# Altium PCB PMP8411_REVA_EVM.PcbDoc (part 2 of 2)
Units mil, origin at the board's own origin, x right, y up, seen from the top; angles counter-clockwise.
Board outline 4000 x 4000 mil, 6 copper layers (Top Layer, Mid-Layer 1, Mid-Layer 2, Mid-Layer 3, Mid-Layer 4, Bottom Layer), stack 118 mil thick; 118 components, 65 nets, 370 pads, 398 vias.
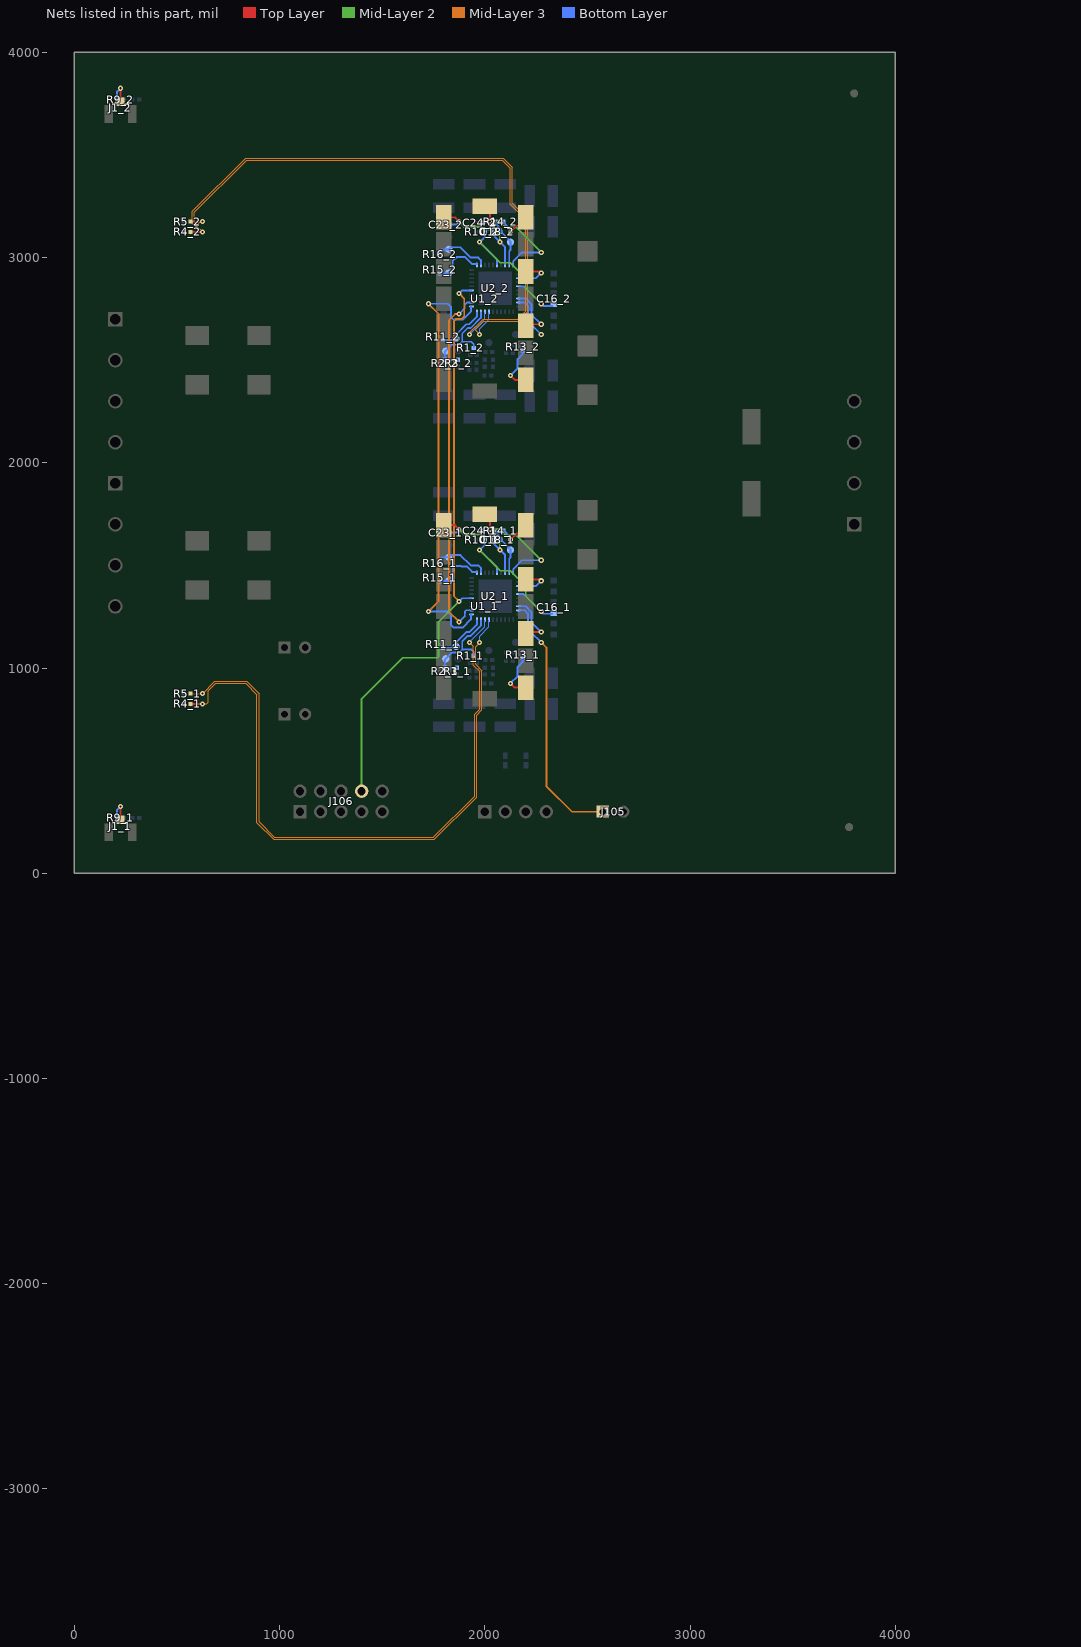
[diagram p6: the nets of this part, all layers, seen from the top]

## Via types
v1: diameter 25, hole 10, Top Layer to Bottom Layer, 378 vias
v2: diameter 19.68, hole 7.87, Top Layer to Bottom Layer, 16 vias
v3: diameter 23, hole 10, Top Layer to Bottom Layer, 4 vias

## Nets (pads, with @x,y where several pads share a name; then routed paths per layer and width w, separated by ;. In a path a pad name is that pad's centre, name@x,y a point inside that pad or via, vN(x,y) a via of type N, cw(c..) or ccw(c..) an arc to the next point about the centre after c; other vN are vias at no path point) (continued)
NetC16_1_1: C16_1.1 R10_1.2 U2_1.16 U2_1.25 | length 859.3
  Mid-Layer 2 w7: v1(1975,1575) 2074.99,1475.01 2124.99,1475.01 2200,1400 2200,1350 v1(2275,1275)
  Bottom Layer w7: v1(2275,1275) 2285.25,1264.75 C16_1.1@2331.25,1264.75
  Bottom Layer w9: R10_1.2@2001.5,1625 2001.5,1601.5 v1(1975,1575) 2059.84,1490.16 U2_1.16@2059.84,1468 ; U2_1.25@2168,1359.84 2190.16,1359.84 v1(2275,1275)
NetC16_2_1: C16_2.1 R10_2.2 U2_2.16 U2_2.25 | length 859.3
  Mid-Layer 2 w7: v1(1975,3075) 2074.99,2975.01 2124.99,2975.01 2200,2900 2200,2850 v1(2275,2775)
  Bottom Layer w9: R10_2.2@2001.5,3125 2001.5,3101.5 v1(1975,3075) 2059.84,2990.16 U2_2.16@2059.84,2968 ; U2_2.25@2168,2859.84 2190.16,2859.84 v1(2275,2775) 2285.25,2764.75 C16_2.1@2331.25,2764.75
NetC18_1_1: C18_1.1 pad.0@2125,1575 R14_1.1 U2_1.19 | length 232.1
  Bottom Layer w9: R14_1.1@2058.5,1670 2058.5,1656.5 2079,1636 2079,1625 2125,1579 pad.0@2125,1575 2125,1537.5 2118.88,1531.38 U2_1.19@2118.88,1468
NetC18_1_2: C18_1.2 C23_1.1 U1_1.7 U2_1.18 | length 578.2
  Top Layer w10: U1_1.7@1799,1696 1854,1696 v1(1875,1675)
  Mid-Layer 2 w10: v1(1875,1675) 1900,1650 1975,1650 1987.5,1637.5 2043.75,1637.5 2075,1606.25 v1(2075,1575)
  Bottom Layer w10: C23_1.1@1826.5,1660 1860,1660 v1(1875,1675) ; C18_1.2@2046,1625 2046,1604 v1(2075,1575) 2099.2,1550.8 U2_1.18@2099.2,1468
NetC18_2_1: C18_2.1 pad.0@2125,3075 R14_2.1 U2_2.19 | length 232.1
  Bottom Layer w9: R14_2.1@2058.5,3170 2058.5,3159 2079,3138.5 2079,3125 2125,3079 pad.0@2125,3075 2125,3037.5 2118.88,3031.38 U2_2.19@2118.88,2968
NetC18_2_2: C18_2.2 C23_2.1 U1_2.7 U2_2.18 | length 578.2
  Top Layer w9: U1_2.7@1799,3196 1854,3196 v1(1875,3175)
  Mid-Layer 2 w10: v1(1875,3175) 1900,3150 1975,3150 1987.5,3137.5 2043.75,3137.5 2075,3106.25 v1(2075,3075)
  Bottom Layer w9: C18_2.2@2046,3125 2046,3104 v1(2075,3075) 2099.2,3050.8 U2_2.18@2099.2,2968
  Bottom Layer w10: C23_2.1@1826.5,3160 1860,3160 v1(1875,3175)
NetC24_1_1: C24_1.1 U1_1.16 U2_1.20 | length 602.5
  Top Layer w9: U1_1.16@2000,1751 2025,1726 v1(2025,1675)
  Mid-Layer 2 w7: v1(2025,1675) 2075,1675 2100,1650 2150,1650 v1(2275,1525)
  Bottom Layer w9: C24_1.1@1991.5,1670 2020,1670 v1(2025,1675) ; U2_1.20@2138.56,1468 2138.56,1482.31 2181.25,1525 v1(2275,1525)
NetC24_2_1: C24_2.1 U1_2.16 U2_2.20 | length 602.5
  Top Layer w9: U1_2.16@2000,3251 2025,3226 v1(2025,3175)
  Mid-Layer 2 w7: v1(2025,3175) 2075,3175 2100,3150 2150,3150 v1(2275,3025)
  Bottom Layer w9: C24_2.1@1991.5,3170 2020,3170 v1(2025,3175) ; U2_2.20@2138.56,2968 2138.56,2982.31 2181.25,3025 v1(2275,3025)
NetJ1_1_1: J1_1.1 R9_1.1 | length 122.3
  Top Layer w9: J1_1.1@225,259.5 v1(225,325)
  Bottom Layer w9: R9_1.1@208.5,275 208.5,308.5 v1(225,325)
NetJ1_2_1: J1_2.1 R9_2.1 | length 122.3
  Top Layer w9: J1_2.1@225,3759.5 v1(225,3825)
  Bottom Layer w9: R9_2.1@208.5,3775 208.5,3808.5 v1(225,3825)
NetR1_1_1: pad.0@1810,1045 R1_1.1 R2_1.2 R3_1.2 U2_1.39 | length 472.5
  Bottom Layer w9: R3_1.2@1865,1001.5 R2_1.2@1805,1001.5 1805,1040 pad.0@1810,1045 1840,1075 1875,1075 1890,1090 ; R1_1.1@1946.5,1060 1946.5,1078.5 1935,1090 1890,1090 ; U2_1.39@1981.12,1232 1981.12,1206.12 1931.73,1156.73 1916.73,1156.73 1890,1130 1890,1090
NetR1_2_1: pad.0@1810,2545 R1_2.1 R2_2.2 R3_2.2 U2_2.39 | length 472.5
  Bottom Layer w9: R3_2.2@1865,2501.5 R2_2.2@1805,2501.5 1805,2540 pad.0@1810,2545 1840,2575 1875,2575 1890,2590 ; R1_2.1@1946.5,2560 1946.5,2578.5 1935,2590 1890,2590 ; U2_2.39@1981.12,2732 1981.12,2706.12 1931.73,2656.73 1916.73,2656.73 1890,2630 1890,2590
NetR4_1_2: R4_1.2 U2_1.37 | length 3144.6
  Top Layer w9: R4_1.2@566.5,825 v1(625,825)
  Mid-Layer 3 w4.49: v1(625,825) 644.49,825 652.67,833.18 652.67,888.53 689.14,925 835.86,925 890,870.86 890,245.86 970.86,165 1754.14,165 1960,370.86 1960,770.86 1985,795.86 1985,987.43 1955,1017.43 1955,1104.14 1975,1124.14 v1(1975,1125)
  Bottom Layer w5: v1(1975,1125) 1975,1155 2020.48,1200.48 U2_1.37@2020.48,1232
NetR4_2_2: R4_2.2 U2_2.37 | length 3056.4
  Top Layer w9: R4_2.2@566.5,3125 v1(625,3125)
  Mid-Layer 3 w4.49: v1(625,3125) 597.68,3152.32 590.86,3152.32 575,3168.18 575,3225 835,3485 2090,3485 2135,3440 2135,3265 2210,3190 2210,2735 2165,2690 1995.5,2690 1952.93,2647.43 1952.93,2647.07 v1(1975,2625)
  Bottom Layer w5: v1(1975,2625) 1975,2653.79 2015.8,2694.59 2015.8,2695.8 2020.48,2700.48 U2_2.37@2020.48,2732
NetR5_1_2: R5_1.2 U2_1.38 | length 3091.6
  Top Layer w5: R5_1.2@566.5,875 v1(625,875)
  Mid-Layer 3 w4.49: v1(625,875) 685,935 840,935 900,875 900,250 975,175 1750,175 1950,375 1950,775 1975,800 1975,983.29 1945,1013.29 1945,1105 v1(1925,1125)
  Bottom Layer w5: v1(1925,1125) 2000.8,1200.8 U2_1.38@2000.8,1232
NetR5_2_2: R5_2.2 U2_2.38 | length 3021.9
  Top Layer w5: R5_2.2@565,3175 R5_2.2@566.5,3175 v1@623.5,3175
  Mid-Layer 3 w4.49: 601.82,3162.32 595,3162.32 585,3172.32 585,3220.86 839.14,3475 2085.86,3475 2125,3435.86 2125,3260.86 2200,3185.86 2200,2739.14 2160.86,2700 1991.36,2700 1925,2633.64 v1(1925,2625) ; v1@614.5,3175 v1(625,3175)
  Mid-Layer 3 w5: 601.82,3162.32 614.5,3175 v1(625,3175)
  Bottom Layer w5: v1(1925,2625) 2000.8,2700.8 U2_2.38@2000.8,2732
NetR11_1_2: pad.0@1860,1105 R11_1.2 U2_1.40 | length 245.5
  Bottom Layer w9: R11_1.2@1795,1098.5 1853.5,1098.5 pad.0@1860,1105 1860,1125 1910,1175 1925,1175 1961.44,1211.44 U2_1.40@1961.44,1232
NetR11_2_2: pad.0@1860,2605 R11_2.2 U2_2.40 | length 245.5
  Bottom Layer w9: R11_2.2@1795,2598.5 1853.5,2598.5 pad.0@1860,2605 1860,2625 1910,2675 1925,2675 1961.44,2711.44 U2_2.40@1961.44,2732
NetR13_1_2: R13_1.2 U1_1.14 | length 233.1
  Top Layer w10: v1(2125,925) 2146,904 U1_1.14@2201,904
  Bottom Layer w10: v1(2125,925) 2160,960 2160,1005 2185,1030 R13_1.2@2185,1048.5
NetR13_2_2: R13_2.2 U1_2.14 | length 233.1
  Top Layer w9: v1(2125,2425) 2146,2404 U1_2.14@2201,2404
  Bottom Layer w9: v1(2125,2425) 2160,2460 2160,2505 2185,2530 R13_2.2@2185,2548.5
NetR14_1_2: R14_1.2 U1_1.8 | length 176
  Top Layer w10: v1(2125,1625) 2155,1655 2180,1655 2201,1676 U1_1.8@2201,1696
  Bottom Layer w10: R14_1.2@2091.5,1670 2125,1636.5 v1(2125,1625)
NetR14_2_2: R14_2.2 U1_2.8 | length 176
  Top Layer w9: v1(2125,3125) 2155,3155 2180,3155 2201,3176 U1_2.8@2201,3196
  Bottom Layer w9: R14_2.2@2091.5,3170 2125,3136.5 v1(2125,3125)
NetR15_1_2: pad.0@1825,1425 R15_1.2 U2_1.11 | length 247.1
  Bottom Layer w9: R15_1.2@1780,1423.5 1823.5,1423.5 pad.0@1825,1425 1843.75,1443.75 1843.75,1483.35 1857.4,1497 1884.11,1497 1886.11,1495 1911.25,1495 1938.25,1468 U2_1.11@1961.44,1468
NetR15_2_2: pad.0@1825,2925 R15_2.2 U2_2.11 | length 251.2
  Bottom Layer w9: R15_2.2@1781.25,2922.25 1822.25,2922.25 pad.0@1825,2925 1843.75,2943.75 1843.75,2983.75 1862.5,3002.5 1903.75,3002.5 1938.25,2968 U2_2.11@1961.44,2968
NetR16_1_2: pad.0@1825,1540 R16_1.2 U2_1.12 | length 254
  Bottom Layer w9: R16_1.2@1781.25,1529 1792.25,1540 pad.0@1825,1540 1835,1550 1881.25,1550 1931.25,1500 1968.75,1500 1981.12,1487.63 U2_1.12@1981.12,1468
NetR16_2_2: pad.0@1825,3040 R16_2.2 U2_2.12 | length 254
  Bottom Layer w9: R16_2.2@1781.25,3029 1792.25,3040 pad.0@1825,3040 1835,3050 1881.25,3050 1931.25,3000 1968.75,3000 1981.12,2987.63 U2_2.12@1981.12,2968
NetU1_1_10: U1_1.10 U2_1.23 | length 194.6
  Top Layer w9: U1_1.10@2201,1432 2268,1432 v1(2275,1425)
  Bottom Layer w9: U2_1.23@2168,1399.2 2249.2,1399.2 v1(2275,1425)
NetU1_1_12: U1_1.12 U2_1.28 | length 265.3
  Top Layer w9: U1_1.12@2201,1168 2208,1175 v1(2275,1175)
  Bottom Layer w9: U2_1.28@2168,1300.8 2199.2,1300.8 2227.5,1272.5 2227.5,1222.5 v1(2275,1175)
NetU1_2_10: U1_2.10 U2_2.23 | length 194.6
  Top Layer w9: U1_2.10@2201,2932 2268,2932 v1(2275,2925)
  Bottom Layer w9: U2_2.23@2168,2899.2 2249.2,2899.2 v1(2275,2925)
NetU1_2_12: U1_2.12 U2_2.28 | length 265.3
  Top Layer w9: U1_2.12@2200,2668 U1_2.12@2207,2675 ; U1_2.12@2208,2675 v1(2275,2675)
  Bottom Layer w9: U2_2.28@2168,2800.8 2199.2,2800.8 2227.5,2772.5 2227.5,2722.5 v1(2275,2675)
PG1: J105.1 U2_1.29 | length 1252.7
  Mid-Layer 3 w9: v1(2275,1125) 2300,1100 2300,425 2425,300 J105.1@2575,300
  Bottom Layer w9: U2_1.29@2168,1281.12 2193.88,1281.12 2210,1265 2210,1210 2225,1195 2225,1175 v1(2275,1125)
PG1_NC: U2_2.29 | length 215.6
  Bottom Layer w9: U2_2.29@2168,2781.12 2193.88,2781.12 2210,2765 2210,2710 2225,2695 2225,2675 v1(2275,2625)
PHSET: U2_1.2 U2_2.2 | length 1737.5
  Mid-Layer 3 w9: v1(1875,1225) 1825,1275 1825,2695 1855,2725 v1(1875,2725)
  Bottom Layer w9: v1(1875,1225) 1903,1253 1903,1254.52 1902.5,1255.02 1902.5,1267.86 1903,1268.36 1903,1275.5 1908.62,1281.12 U2_1.2@1932,1281.12 ; v1(1875,2725) 1902.5,2752.5 1902.5,2770 1913.62,2781.12 U2_2.2@1932,2781.12
SMBAL: J106.8 U2_1.5 U2_2.5 | length 2904.8
  Mid-Layer 2 w9: J106.8@1400,400 1400,850 1600,1050 1770.5,1050 1775,1054.5 1775,1225 v1(1875,1325)
  Mid-Layer 3 w9: v1(1875,1325) 1850,1350 1850,2690 1860,2700 1886,2700 1900,2714 1900,2800 v1(1875,2825)
  Bottom Layer w9: v1(1875,1325) 1890.16,1340.16 U2_1.5@1932,1340.16 ; v1(1875,2825) 1890.16,2840.16 U2_2.5@1932,2840.16
SYNC: U2_1.1 U2_2.1 | length 2160.2
  Mid-Layer 3 w9: v1(1725,1275) 1775,1325 1775,2725 v1(1725,2775)
  Bottom Layer w9: v1(1725,1275) 1820,1275 1835,1260 1835,1210 1848,1197 1892,1197 1932,1237 U2_1.1@1932,1261.44 ; v1(1725,2775) 1820,2775 1835,2760 1835,2710 1847.5,2697.5 1892.5,2697.5 1932,2737 U2_2.1@1932,2761.44
pads on no net: FID100.1 FID101.1 J106.1 J106.2 J106.3 J106.4 U2_1.4 U2_1.22 U2_2.4 U2_2.22

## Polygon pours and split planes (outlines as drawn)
+1.0V on Bottom Layer "BOTTOM-P0_9V_SM0_VDD" (solid, pour order 2): 1675,675 1675,1900 2155,1900 2155,1805 1740,1805 1740,1560 1740,1555 1740,1415 1730,1405 1710,1405 1700,1395 1700,1380.04 1699.96,1379.85 1699.64,1377.65 1699.5,1375.43 1699.56,1373.2 1699.81,1370.99 1699.96,1370.15 1700,1369.96 1700,1330.04 1699.96,1329.85 1699.64,1327.65 1699.5,1325.43 1699.56,1323.2 1699.81,1320.99 1699.96,1320.15 1700,1319.96 1700,1280.04 1699.96,1279.85 1699.64,1277.65 1699.5,1275.43 1699.56,1273.2 1699.81,1270.99 1699.96,1270.15 1700,1269.96 1700,1210 1710,1200 1770,1200 1770,995 1740,965 1740,790 2155,790 2155,675 1675,675
+1.0V on Bottom Layer "BOTTOM-P0_9V_SM0_VDD 1" (solid, pour order 8): 1675,2175 1675,3400 2155,3400 2155,3305 1740,3305 1740,3060 1740,3055 1740,2915 1730,2905 1710,2905 1700,2895 1700,2880.04 1699.96,2879.85 1699.64,2877.65 1699.5,2875.43 1699.56,2873.2 1699.81,2870.99 1699.96,2870.15 1700,2869.96 1700,2830.04 1699.96,2829.85 1699.64,2827.65 1699.5,2825.43 1699.56,2823.2 1699.81,2820.99 1699.96,2820.15 1700,2819.96 1700,2780.04 1699.96,2779.85 1699.64,2777.65 1699.5,2775.43 1699.56,2773.2 1699.81,2770.99 1699.96,2770.15 1700,2769.96 1700,2710 1710,2700 1770,2700 1770,2495 1740,2465 1740,2290 2155,2290 2155,2175 1675,2175
+1.0V on Bottom Layer "BOTTOM-P0_9V_SM0_VDD 2" (solid, pour order 12): 1700,2869.96 1700,2830.04 1699.96,2829.85 1699.64,2827.65 1699.5,2825.43 1699.56,2823.2 1699.81,2820.99 1699.96,2820.15 1700,2819.96 1700,2780.04 1699.96,2779.85 1699.64,2777.65 1699.5,2775.43 1699.56,2773.2 1699.81,2770.99 1699.96,2770.15 1700,2769.96 1700,2200 2075,2200 2075,1875 1700,1875 1700,1380.04 1699.96,1379.85 1699.64,1377.65 1699.5,1375.43 1699.56,1373.2 1699.81,1370.99 1699.96,1370.15 1700,1369.96 1700,1330.04 1699.96,1329.85 1699.64,1327.65 1699.5,1325.43 1699.56,1323.2 1699.81,1320.99 1699.96,1320.15 1700,1319.96 1700,1280.04 1699.96,1279.85 1699.64,1277.65 1699.5,1275.43 1699.56,1273.2 1699.81,1270.99 1699.96,1270.15 1700,1269.96 1700,675 1494.59,675 1494.42,676.81 1494.19,678.5 1493.81,680.16 1493.29,681.78 1492.63,683.35 1491.83,684.85 1490.91,686.28 1489.87,687.62 1488.71,688.87 1487.45,690.01 1486.09,691.04 1484.65,691.95 1483.14,692.72 1481.56,693.36 1479.94,693.87 1478.27,694.23 1476.59,694.44 1474.89,694.5 1473.19,694.42 1471.5,694.19 1469.84,693.81 1468.22,693.29 1466.65,692.63 1465.15,691.83 1463.72,690.91 1462.38,689.87 1461.13,688.71 1459.99,687.45 1458.96,686.09 1458.05,684.65 1457.28,683.14 1456.64,681.56 1456.13,679.94 1455.77,678.27 1455.58,676.81 1455.41,675 1300,675 1300,1600 100,1600 100,2400 1300,2400 1300,3400 1700,3400 1700,2880.04 1699.96,2879.85 1699.64,2877.65 1699.5,2875.43 1699.56,2873.2 1699.81,2870.99 1699.96,2870.15 1700,2869.96
IBV on Bottom Layer "BOTTOM-IBV" (solid, pour order 20): 2350,675 2350,1000 2410,1000 2410,875 2590,875 2590,1000 2700,1000 2700,1600 2590,1600 2590,1725 2410,1725 2410,1600 2350,1600 2350,2500 2410,2500 2410,2375 2590,2375 2590,2500 2700,2500 2700,3100 2590,3100 2590,3225 2410,3225 2410,3100 2350,3100 2350,3400 3000,3400 3000,2500 3900,2500 3900,2000 3000,2000 3000,675 2350,675
IBV on Bottom Layer "BOTTOM-IBV 1" (solid, pour order 24): 2260,3050 2260,3065 2260,3400 2375,3400 2375,3050 2280.04,3050 2279.85,3050.04 2277.65,3050.36 2275.43,3050.5 2273.2,3050.44 2270.99,3050.19 2270.15,3050.04 2269.96,3050 2260,3050
IBV on Bottom Layer "BOTTOM-IBV 2" (solid, pour order 26): 2260,2175 2260,2510 2260,2540 2307.68,2540 2375,2540 2375,2175 2260,2175
IBV on Bottom Layer "BOTTOM-IBV 3" (solid, pour order 32): 2260,675 2260,1040 2307.68,1040 2375,1040 2375,675 2260,675
IBV on Bottom Layer "BOTTOM-IBV 4" (solid, pour order 34): 2260,1550 2260,1900 2375,1900 2375,1550 2280.04,1550 2279.85,1550.04 2277.65,1550.36 2275.43,1550.5 2273.2,1550.44 2270.99,1550.19 2270.15,1550.04 2269.96,1550 2260,1550
GND on Bottom Layer "BOTTOM-GND" (solid, pour order 48): 2175,625 2175,700 2250,700 2250,665 2250,625 2175,625
GND on Bottom Layer "BOTTOM-GND 1" (solid, pour order 50): 2175,3375 2175,3450 2250,3450 2250,3410 2250,3375 2175,3375
GND on Bottom Layer "BOTTOM-GND 2" (solid, pour order 52): 2175,1875 2175,1950 2250,1950 2250,1910 2250,1875 2175,1875
GND on Bottom Layer "BOTTOM-GND 3" (solid, pour order 54): 2175,2125 2175,2200 2250,2200 2250,2165 2250,2125 2175,2125
GND on Bottom Layer "BOTTOM-GND 4" (solid, pour order 56): 2325,2150 2325,1925 2100,1925 2100,2150 2325,2150
GND on Bottom Layer "BOTTOM-GND 5" (solid, pour order 58): 2400,2525 2400,3075 2410,3075 2590,3075 2675,3075 2675,2525 2590,2525 2410,2525 2400,2525
GND on Bottom Layer "BOTTOM-GND 6" (solid, pour order 60): 2400,1025 2400,1575 2410,1575 2590,1575 2675,1575 2675,1025 2590,1025 2410,1025 2400,1025
GND on Bottom Layer "BOTTOM-GND 7" (solid, pour order 64): 2155,1575 2155,1630 2146.85,1638.15 2145.62,1640 2144.23,1641.74 2142.7,1643.36 2141.03,1644.83 2139.25,1646.15 2138.35,1646.73 2138.15,1646.85 2115,1670 2115,1690 2105,1700 1850,1700 1835,1685 1750,1685 1750,1795 2165,1795 2165,1900 2250,1900 2250,1575 2155,1575
GND on Bottom Layer "BOTTOM-GND 8" (solid, pour order 66): 2165,675 2165,800 1750,800 1750,890 2155,890 2185,920 2185,1000 2250,1000 2250,675 2165,675
GND on Bottom Layer "BOTTOM-GND 9" (solid, pour order 76): 100,100 100,1575 510,1575 510,1425 690,1425 690,1575 810,1575 810,1425 990,1425 990,1575 1275,1575 1275,650 3025,650 3025,1975 3900,1975 3900,100 100,100
GND on Bottom Layer "BOTTOM-GND 10" (solid, pour order 78): 100,2425 100,3900 3900,3900 3900,2525 3025,2525 3025,3425 1275,3425 1275,2425 990,2425 990,2575 810,2575 810,2425 690,2425 690,2575 510,2575 510,2425 100,2425
GND on Bottom Layer "BOTTOM-GND 11" (solid, pour order 80): 2165,2175 2165,2300 1750,2300 1750,2390 2155,2390 2185,2420 2185,2500 2250,2500 2250,2175 2165,2175
GND on Bottom Layer "BOTTOM-GND 12" (solid, pour order 82): 2155,3075 2155,3130 2146.85,3138.15 2146.73,3138.35 2145.48,3140.19 2144.08,3141.92 2142.54,3143.52 2140.85,3144.97 2139.05,3146.28 2138.35,3146.73 2138.15,3146.85 2115,3170 2115,3190 2105,3200 1850,3200 1835,3185 1750,3185 1750,3295 2165,3295 2165,3400 2250,3400 2250,3075 2155,3075
+1.0V on Top Layer "TOP-P0_9V_SM0_VDD" (solid, pour order 4): 1675,675 1675,1900 2075,1900 2075,1800 1850,1800 1850,1755 1755,1755 1755,1753.5 1754,1753.5 1754,1638.5 1755,1638.5 1755,1495 1850,1495 1850,1360 1755,1360 1755,1400 1700,1400 1700,1360 1700,1300 1700,1250 1700,1200 1755,1200 1755,1225 1770,1240 1850,1240 1850,1105 1755,1105 1755,961.5 1754,961.5 1754,846.5 1755,846.5 1755,840 1850,840 1850,800 2075,800 2075,675 1675,675
+1.0V on Top Layer "TOP-P0_9V_SM0_VDD 1" (solid, pour order 6): 1675,2175 1675,3400 2075,3400 2075,3300 1850,3300 1850,3255 1755,3255 1755,3253.5 1754,3253.5 1754,3138.5 1755,3138.5 1755,2995 1850,2995 1850,2860 1755,2860 1755,2900 1700,2900 1700,2860 1700,2800 1700,2750 1700,2700 1755,2700 1755,2725 1770,2740 1850,2740 1850,2605 1755,2605 1755,2461.5 1754,2461.5 1754,2346.5 1755,2346.5 1755,2340 1850,2340 1850,2300 2075,2300 2075,2175 1675,2175
+1.0V on Top Layer "TOP-P0_9V_SM0_VDD 2" (solid, pour order 14): 1455.41,675 1300,675 1300,1600 100,1600 100,2400 1300,2400 1300,3400 1700,3400 1700,2200 2075,2200 2075,2165 2075,1910 2075,1875 1700,1875 1700,675 1494.59,675 1494.42,676.81 1494.19,678.5 1493.81,680.16 1493.29,681.78 1492.63,683.35 1491.83,684.85 1490.91,686.28 1489.87,687.62 1488.71,688.87 1487.45,690.01 1486.09,691.04 1484.65,691.95 1483.14,692.72 1481.56,693.36 1479.94,693.87 1478.27,694.23 1476.59,694.44 1474.89,694.5 1473.19,694.42 1471.5,694.19 1469.84,693.81 1468.22,693.29 1466.65,692.63 1465.15,691.83 1463.72,690.91 1462.38,689.87 1461.13,688.71 1459.99,687.45 1458.96,686.09 1458.05,684.65 1457.28,683.14 1456.64,681.56 1456.13,679.94 1455.77,678.27 1455.58,676.81 1455.41,675
IBV on Top Layer "TOP-IBV" (solid, pour order 28): 2250,2175 2250,2355 2250,2465 2150,2465 2150,2600 2375,2600 2375,2175 2250,2175
IBV on Top Layer "TOP-IBV 1" (solid, pour order 30): 2250,1900 2375,1900 2375,1550 2265,1550 2250,1535 2250,1495 2155,1495 2155,1635 2250,1635 2250,1900
IBV on Top Layer "TOP-IBV 2" (solid, pour order 36): 2350,675 2350,1000 2410,1000 2410,875 2590,875 2590,1000 2700,1000 2700,1600 2590,1600 2590,1725 2410,1725 2410,1600 2350,1600 2350,2500 2410,2500 2410,2375 2590,2375 2590,2500 2700,2500 2700,3100 2590,3100 2590,3225 2410,3225 2410,3100 2350,3100 2350,3400 3000,3400 3000,2500 3900,2500 3900,2000 3332,2000 3332,2050 3268,2050 3268,2000 3000,2000 3000,675 2350,675
IBV on Top Layer "TOP-IBV 3" (solid, pour order 38): 2150,965 2150,1100 2375,1100 2375,675 2250,675 2250,965 2150,965
IBV on Top Layer "TOP-IBV 4" (solid, pour order 40): 2155,2995 2155,3110 2155,3135 2250,3135 2250,3245 2250,3400 2375,3400 2375,3050 2265.86,3050 2265,3050 2250,3035 2250,3034.15 2250,3034.14 2250,2995 2155,2995
GND on Top Layer "TOP-GND" (solid, pour order 42): 2100,1875 2100,2200 2240,2200 2240,2165 2325,2165 2325,1910 2240,1910 2240,1875 2100,1875
GND on Top Layer "TOP-GND 1" (solid, pour order 44): 2385,1025 2385,1110 2350,1110 2350,1540 2385,1540 2385,1575 2410,1575 2590,1575 2675,1575 2675,1025 2590,1025 2410,1025 2385,1025
GND on Top Layer "TOP-GND 2" (solid, pour order 46): 2385,2525 2385,2610 2350,2610 2350,3040 2385,3040 2385,3075 2410,3075 2590,3075 2675,3075 2675,2525 2590,2525 2410,2525 2385,2525
GND on Top Layer "TOP-GND 3" (solid, pour order 68): 2090,630 2090,700 2240,700 2240,665 2240,630 2090,630
GND on Top Layer "TOP-GND 4" (solid, pour order 70): 2240,3450 2240,3360 2090,3360 2090,3450 2240,3450
GND on Top Layer "TOP-GND 5" (solid, pour order 72): 100,100 100,1575 510,1575 510,1425 690,1425 690,1575 810,1575 810,1425 990,1425 990,1575 1275,1575 1275,650 3025,650 3025,1975 3268,1975 3268,1950 3332,1950 3332,1975 3900,1975 3900,100 100,100
GND on Top Layer "TOP-GND 6" (solid, pour order 74): 100,2425 100,3900 3900,3900 3900,2525 3025,2525 3025,3425 1275,3425 1275,2425 990,2425 990,2575 810,2575 810,2425 690,2425 690,2575 510,2575 510,2425 100,2425
GND on Top Layer "TOP-GND 7" (solid, pour order 84): 964 vertices, not listed, extent 1765,2175 2375,3400
GND on Top Layer "TOP-GND 8" (solid, pour order 86): 963 vertices, not listed, extent 1765,675 2375,1900
+1.0V on Mid-Layer 4 "P05-P0_9V_SM0_VDD" (solid, pour order 10): 2200,100 100,100 100,3900 2200,3900 2200,100
IBV on Mid-Layer 4 "P05-IBV" (solid, pour order 16): 2250,700 2550,700 2550,850 2425,850 2425,1775 2575,1775 2575,1925 2250,1925 2250,700
IBV on Mid-Layer 4 "P05-IBV 1" (solid, pour order 18): 2250,2200 2550,2200 2550,2350 2425,2350 2425,3275 2575,3275 2575,3425 2250,3425 2250,2200
IBV on Mid-Layer 4 "P05-IBV 2" (solid, pour order 22): 2210,338.73 2210,3900 3900,3900 3900,100 2210,100 2210,261.27 2213.34,262.29 2216.58,263.59 2219.69,265.18 2222.65,267.03 2225.43,269.12 2228.03,271.46 2230.41,274.01 2232.56,276.76 2234.46,279.69 2236.1,282.77 2237.46,285.98 2238.54,289.3 2239.33,292.7 2239.82,296.15 2240,299.64 2239.88,303.12 2239.46,306.59 2238.73,310 2237.71,313.34 2236.41,316.58 2234.82,319.69 2232.97,322.65 2230.88,325.43 2228.54,328.03 2225.99,330.41 2223.24,332.56 2220.31,334.46 2217.23,336.1 2214.02,337.46 2210.7,338.54 2210,338.73
GND on Mid-Layer 1 "G02-GND" (solid, pour order 62): 3900,100 100,100 100,3900 3900,3900 3900,100

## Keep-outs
Keep-Out Layer:
  lines w10: -5,0 ccw(c0,0) 0,-5 ; -5,0 ccw(c0,0) 0,-5 ; -5,0 ccw(c0,0) 0,-5 ; -5,0 ccw(c0,0) 0,-5 ; -5,0 -5,4000 ; -5,4000 cw(c0,4000) 0,4005 ; -5,4000 cw(c0,4000) 0,4005 ; 0,-5 4000,-5 ; 0,4005 4000,4005 ; 4000,-5 ccw(c4000,0) 4005,0 ; 4000,-5 ccw(c4000,0) 4005,0 ; 4000,4005 cw(c4000,4000) 4005,4000 ; 4000,4005 cw(c4000,4000) 4005,4000 ; 4005,0 4005,4000
  text ".Layer_Name" at 577,-858.49 h60

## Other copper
Top Layer:
  text "©" at 3125,125 h105
  text ".CopyrightYear" at 3225,125 h60
  text "TI" at 3501,125 h60
  text ".Layer_Name" at 577,-858.49 h60
Bottom Layer:
  text "UL94V-0" at 1830,120 h60
  text ".VersionControl_RevNumber" at 3430,120 h60
  text "SVN:" at 3880,120 h60
  text "MADE IN U.S." at 1125,115 h60
  text ".Layer_Name" at 577,-858.49 h60
Multi-Layer:
  lines w1: 100,100 3900,100 ; 100,100 100,3900 ; 100,100 3900,100 ; 100,100 100,3900 ; 100,3900 3900,3900 ; 100,3900 3900,3900 ; 3900,100 3900,3900 ; 3900,100 3900,3900

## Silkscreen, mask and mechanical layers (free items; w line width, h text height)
Top Overlay:
  region: 3550,3775 3250,3775 3250,3675 3550,3675
  lines w7: 1675,675 1675,1900 2375,1900 2375,675 1675,675 ; 1675,2175 2375,2175 2375,3400 1675,3400 1675,2175 ; 4042,-3525 4742,-3525 4742,-2300 4042,-2300 4042,-3525
  text ".PRJ_Number" at 2750,3700 h60
  text ".PCB_Rev" at 3150,3700 h60
  text "-" at 3200,3700 h60
  text ".Layer_Name" at 577,-858.49 h60
Bottom Overlay:
  lines w7: 1675,675 1675,1900 2375,1900 2375,675 1675,675 ; 1675,2175 1675,3400 2375,3400 2375,2175 1675,2175
  text ".Layer_Name" at 577,-858.49 h60
Top Paste:
  text ".Layer_Name" at 577,-858.49 h60
Bottom Paste:
  text ".Layer_Name" at 577,-858.49 h60
Top Solder:
  text ".Layer_Name" at 577,-858.49 h60
  text ".Layer_Name" at 577,-858.49 h60
Bottom Solder:
  text ".Layer_Name" at 577,-858.49 h60
Drill Guide:
  text ".Layer_Name" at 577,-858.49 h60
M1 Board Outline:
  the board outline again, w10
  text ".Layer_Name" at 577,-858.49 h60
M2 Board Dimensions:
  rectangle: 125,-400 500,-275
  rectangle: 0,-275 125,-150
  lines w7: 0,-275 1000,-275 ; 125,-400 125,-150 ; 250,-400 250,-150 ; 500,-400 500,-150 ; 750,-400 750,-150 ; 0,-400 0,-150 1000,-150 1000,-400 0,-400
  text ".Layer_Name" at 577,-858.49 h60
M3 3D STEP Top:
  text ".Layer_Name" at 577,-858.49 h60
M4 3D STEP Bottom:
  text ".Layer_Name" at 577,-858.49 h60
M5 Assembly Top:
  lines w10: -292,-930.17 6308,-930.17 ; -292,-726.83 6310,-726.83 ; -292,-523.5 -292,-1133.5 3713,-1133.5 6310,-1133.5 6310,-523.5 -291.5,-523.5 -291.5,-1133.5 1284,-1133.5 ; 2173,-1133.5 2173,-523.5 ; 3440,-726.83 3440,-523.5 ; 4280,-726.83 4280,-523.5 ; 4902,-1140 4902,-937.17
  text "COMPONENTS MARKED 'DNP' SHOULD NOT BE POPULATED." at 1153.5,-318.5 h60
  text "ASSEMBLY VARIANT:" at 1153,-434 h60
  text ".VariantName" at 2189,-434 h60
  text "PCB VIEWED FROM TOP SIDE" at -228.5,-655.67 h60
  text "BOARD #:" at 2248,-655.67 h60
  text ".PRJ_Number" at 2793.5,-655.67 h60
  text "REV:" at 3638,-655.67 h60
  text ".PCB_Rev" at 3929.5,-655.67 h60
  text "SVN REV:" at 4476,-655.67 h60
  text ".VersionControl_RevNumber" at 4982,-655.67 h60
  text "PLOT NAME =" at -228.5,-1064.34 h60
  text ".plot_File_Name" at 577,-1064.34 h60
  text "GENERATED    :" at 2250,-1064.34 h60
  text ".Print_Date" at 3119.5,-1064.34 h60
  text ".Print_Time" at 3848.5,-1064.34 h60
  text "TEXAS INSTRUMENTS" at 5113,-1064.34 h60
M6 Assembly Bottom:
  lines w10: -292.5,-727.33 6309.5,-727.33 ; -290.5,-930.67 6309.5,-930.67 ; 1115.5,-1140.5 1115.5,-937.67 ; 1737.5,-727.33 1737.5,-524 ; 2577.5,-727.33 2577.5,-524 ; 3844.5,-1134 3844.5,-524 ; 4733.5,-1134 6309,-1134 6309,-524 -292.5,-524 -292.5,-1134 2304.5,-1134 6309.5,-1134 6309.5,-524
  text "COMPONENTS MARKED 'DNP' SHOULD NOT BE POPULATED." at 6102,-318 h60
  text ".VariantName" at 5058,-434 h60
  text "ASSEMBLY VARIANT:" at 6097,-434 h60
  text ".VersionControl_RevNumber" at 1035.5,-656.17 h60
  text "SVN REV:" at 1541.5,-656.17 h60
  text ".PCB_Rev" at 2088,-656.17 h60
  text "REV:" at 2379.5,-656.17 h60
  text ".PRJ_Number" at 3224,-656.17 h60
  text "BOARD #:" at 3769.5,-656.17 h60
  text "PCB VIEWED FROM BOTTOM SIDE" at 6246,-656.17 h60
  text "TEXAS INSTRUMENTS" at 904.5,-1064.84 h60
  text ".Print_Time" at 2169,-1064.84 h60
  text ".Print_Date" at 2898,-1064.84 h60
  text "GENERATED    :" at 3767.5,-1064.84 h60
  text ".plot_File_Name" at 5440.5,-1064.84 h60
  text "PLOT NAME =" at 6246,-1064.84 h60
M9 Title Sheet:
  drawing of 57 lines, arcs and shapes, not listed
  text "1" at 739.84,8036.5 h70
  text "2" at 3235.5,8036.5 h70
  text "3" at 5724.84,8036.5 h70
  text "4" at 8231.51,8036.5 h70
  text "5" at 10730.5,8036.5 h70
  text "6" at 13235.5,8036.5 h70
  text "A" at -416.5,6893.5 h70
  text "A" at 14383.5,6893.5 h70
  text "B" at -416.5,4513.5 h70
  text "B" at 14383.5,4513.5 h70
  text "C" at -416.5,2138.5 h70
  text "C" at 14383.5,2138.5 h70
  text "PROJECT TITLE:" at 11343.5,277.5 h45
  text ".PRJ_Title" at 11393.5,144.17 h70
  text "DESIGNED FOR:" at 11343.5,-23.5 h45
  text ".PRJ_Customer" at 11393.5,-163.5 h70
  text "D" at -416.5,-231.5 h70
  text "D" at 14383.5,-231.5 h70
  text "FILE NAME:" at 11343.5,-323.5 h45
  text ".PCB_File_Name_No_Path" at 11393.5,-443.5 h70
  text "Texas Instruments (TI) and/or its licensors do not warrant the accuracy or completeness of this specification" at 6374,-605.34 h45
  text "ENGINEER:" at 11343.5,-613.5 h45
  text "LAYOUT BY:" at 12848.5,-613.5 h45
  text "or any information contained therein. TI and/or its licensors do not warrant that this design will meet" at 6329.01,-718 h45
  text ".PRJ_Engineer" at 11393.5,-768.49 h70
  text ".PCB_Layout" at 12899,-768.49 h70
  text "the specifications, will be suitable for your application or fit for any particular purpose, or will operate in" at 6329.01,-830.67 h45
  text ".Layer_Name" at 577,-858.49 h60
  text "ALTIUM DESIGNER VERSION:" at 12848.5,-923.5 h45
  text "an implementation. TI and/or its licensors do not warrant that the design is production worthy. You should" at 6329.01,-943.33 h45
  text "completely validate and test your design implementation to confirm the system functionality for your application." at 6374,-1056 h45
  text ".print_Scale" at 11393.5,-1056.83 h70
  text ".Application_BuildNumber" at 12899,-1056.83 h70
  text "1" at 739.84,-1263.5 h70
  text "2" at 3235.5,-1263.5 h70
  text "3" at 5724.84,-1263.5 h70
  text "4" at 8231.51,-1263.5 h70
  text "5" at 10730.5,-1263.5 h70
  text "6" at 13235.5,-1263.5 h70
M10 Fab Notes:
  drawing of 185 lines, arcs and shapes, not listed
  text "DESIGN INFORMATION" at 12381.02,5910 h60
  text "MIN. TRACK WIDTH:" at 11736.46,5730 h60
  text "8" at 12832.7,5730 h60
  text "MIL" at 12987.46,5730 h60
  text "MIN. CLEARANCE:" at 11736.46,5598 h60
  text "0.2" at 12772.7,5598 h60
  text "mm" at 12987.46,5598 h60
  text "MIN. VIA PAD SIZE:" at 11736.46,5466 h60
  text "24" at 12802.71,5466 h60
  text "MIL" at 12987.46,5466 h60
  text "0.05mm (2MIL)" at 12431.46,5324.29 h60
  text "MINIMUM ANNULAR RING" at 11407.23,5320 h60
  text "EXTERNAL" at 13139.46,5320 h60
  text "PER" at 11607.23,5202 h60
  text "IPC-D-275 CLASS 2 LEVEL C" at 11827.23,5202 h60
  text "MIL, HOLES" at 13315.46,5089.71 h60
  text "+/-" at 12923,5089 h60
  text "+/-" at 13777,5089 h60
  text "REGISTRATION TOLERANCES:" at 11407.23,5084 h60
  text "METAL" at 12607,5084 h60
  text "5" at 13183.2,5084 h60
  text "3" at 14016.2,5084 h60
  text "MIL" at 14132.46,5084 h60
  text "MATERIAL:" at 11332.46,4874.54 h60
  text "FR-4 High Tg" at 12318.9,4734.21 h60
  text "FR-408" at 11753.46,4725.64 h60
  text "X" at 12165.46,4725.64 h60
  text "OTHER" at 13241.46,4725.64 h60
  text "62 MIL (1.6mm) +/-10%" at 12073.56,4562.92 h60
  text "THICKNESS:" at 11407.23,4558.64 h60
  text "X" at 11945.4,4558.64 h60
  text "OTHER" at 13358.46,4558.64 h60
  text "TOLERANCE:" at 11407.23,4400.64 h60
  text "X" at 12246.53,4400.64 h60
  text "ANSI IPC-6012 TYPE 3 CLASS 2" at 12433.48,4400.64 h60
  text "OTHER +/-" at 12433.46,4244.64 h60
  text "BOW & TWIST:" at 11407.23,4087.64 h60
  text "X" at 12246.53,4087.64 h60
  text "ANSI IPC-6012 TYPE 3 CLASS 2" at 12433.48,4087.64 h60
  text "OTHER +/-" at 12433.46,3929.13 h60
  text "DRILLING:" at 11332.46,3790.64 h60
  text "REFERENCE:" at 11407.23,3673.64 h60
  text "X" at 12055.46,3673.64 h60
  text "AS SHOWN" at 12242.46,3673.64 h60
  text "X" at 12956.46,3673.64 h60
  text "NC_DRILL FILES" at 13093.46,3673.64 h60
  text "PTH MIN COPPER THICKNESS:" at 11407.23,3515.64 h60
  text "X" at 12757.46,3515.64 h60
  text "1MIL" at 12894.46,3515.64 h60
  text "OTHER" at 13391.46,3515.64 h60
  text "BOARD FINISH:" at 11332.46,3356.64 h60
  text "SILKSCREEN:" at 11487.68,3238.64 h60
  text "X" at 12436.46,3238.64 h60
  text "TOP" at 12562.46,3238.64 h60
  text "X" at 12946.46,3238.64 h60
  text "BOTTOM" at 13073.46,3238.64 h60
  text "SILKSCREEN COLOR:" at 11487.68,3071.64 h60
  text "X" at 12435.42,3071.64 h60
  text "WHITE" at 12562.46,3071.64 h60
  text "OTHER" at 13073.46,3071.64 h60
  text "SOLDER RESIST COLOR:" at 11487.68,2901.64 h60
  text "X" at 12055.42,2742.44 h60
  text "GREEN" at 12182.46,2742.44 h60
  text "BLUE" at 12773.46,2742.44 h60
  text "OTHER" at 13311.46,2742.44 h60
  text "IMMERSION GOLD (ENIG)" at 12393.46,2553.92 h60
  text "ENEPIG" at 13731,2550.64 h60
  text "SURFACE FINISH:" at 11332.46,2549.64 h60
  text "X" at 12206.51,2549.64 h60
  text "IMM. TIN/SILVER OR EQUIV" at 11662,2392.64 h60
  text "OTHER" at 13093.46,2392.64 h60
  text "ARRAY/PANEL:" at 11332.46,2213.64 h60
  text "CUT AND TRIM PER MECH LAYER 1" at 12393.46,2209.35 h60
  text "N.C. ROUTE" at 12393.46,2057.64 h60
  text "X" at 13072.46,2057.64 h60
  text "V. SCORE" at 13259.46,2057.64 h60
  text "CERTIFICATION:" at 11332.46,1920.64 h60
  text "MATERIALS AND WORKMANSHIP FOR ALL PCBS" at 12057.46,1920.64 h60
  text "TO MEET OR EXCEED THE REQUIREMENTS OF:" at 12057.46,1822.64 h60
  text "X" at 11683.96,1686.13 h60
  text "ANSI IPC-A-600F CLASS ->" at 11822.96,1686.13 h60
  text "X" at 13462.02,1686.13 h60
  text "2" at 13580.96,1686.14 h60
  text "1" at 13265.96,1684.64 h60
  text "3" at 13934.96,1684.64 h60
  text "X" at 11686.02,1526.64 h60
  text "UL 94V-0" at 11822.96,1526.64 h60
  text "X" at 12498.02,1526.64 h60
  text "RoHS" at 12634.96,1526.64 h60
  text "OTHER" at 13279.36,1526.64 h60
  text "PER ORDER" at 13676.42,1526.64 h60
  text "ADDITIONAL REQUIREMENTS:" at 11332.46,1385.64 h60
  text "MICROSECTION:" at 11407.23,1270.64 h60
  text "YES" at 12312.96,1270.64 h60
  text "REQUIRED" at 13174.46,1114.49 h60
  text "BARE BOARD ELEC. TEST:" at 11407.23,1111.64 h60
  text "NONE" at 12712.96,1111.64 h60
  text "X" at 13047.46,1111.64 h60
  text "PER ORDER" at 13766.46,1111.64 h60
  text "MANUFACTURER'S UL:" at 11407.23,954.64 h60
  text "RAIL" at 12572.96,950.35 h60
  text "METAL" at 13064.77,950.35 h60
  text "X" at 13440,950 h60
  text "SILK" at 13576.46,950.35 h60
  text ".Layer_Name" at 577,-858.49 h60
M11 Gerber Information:
  lines w10: -292,-930.17 6308,-930.17 ; -292,-726.83 6310,-726.83 ; -292,-523.5 -292,-1133.5 3713,-1133.5 6310,-1133.5 6310,-523.5 -291.5,-523.5 -291.5,-1133.5 1284,-1133.5 ; 2173,-1133.5 2173,-523.5 ; 3440,-726.83 3440,-523.5 ; 4280,-726.83 4280,-523.5 ; 4902,-1140 4902,-937.17
  text "ALL ARTWORK VIEWED FROM TOP SIDE" at -228.5,-655.67 h60
  text "BOARD #:" at 2248,-655.67 h60
  text ".PRJ_Number" at 2793.5,-655.67 h60
  text "REV:" at 3638,-655.67 h60
  text ".PCB_Rev" at 3929.5,-655.67 h60
  text "SVN REV:" at 4476,-655.67 h60
  text ".VersionControl_RevNumber" at 4982,-655.67 h60
  text "LAYER NAME =" at -228.5,-858.49 h60
  text "PLOT NAME =" at -228.5,-1064.34 h60
  text ".plot_File_Name" at 577,-1064.34 h60
  text "GENERATED    :" at 2250,-1064.34 h60
  text ".Print_Date" at 3119.5,-1064.34 h60
  text ".Print_Time" at 3848.5,-1064.34 h60
  text "TEXAS INSTRUMENTS" at 5113,-1064.34 h60
M12 Stackup:
  drawing of 191 lines, arcs and shapes, not listed
  text "Layer" at 9790.34,7830 h60
  text "Name" at 10200.26,7830 h60
  text "Material" at 11130,7830 h60
  text "Thickness" at 11989.77,7830 h60
  text "Constant" at 12639.6,7830 h60
  text "Board Layer Stack" at 13209.46,7830 h60
  text "1" at 9790.34,7710 h60
  text "Top Overlay" at 10200.26,7710 h60
  text "2" at 9790.34,7590 h60
  text "Top Solder" at 10200.26,7590 h60
  text "Solder Resist" at 11130,7590 h60
  text "0.40mil" at 11989.77,7590 h60
  text "3.5" at 12639.6,7590 h60
  text "3" at 9790.34,7470 h60
  text "Top Layer" at 10200.26,7470 h60
  text "Copper" at 11130,7470 h60
  text "1.40mil" at 11989.77,7470 h60
  text "4" at 9790.34,7350 h60
  text "Dielectric1" at 10200.26,7350 h60
  text "FR-4" at 11130,7350 h60
  text "59.20mil" at 11989.77,7350 h60
  text "4.8" at 12639.6,7350 h60
  text "5" at 9790.34,7230 h60
  text "Bottom Layer" at 10200.26,7230 h60
  text "Copper" at 11130,7230 h60
  text "1.40mil" at 11989.77,7230 h60
  text "6" at 9790.34,7110 h60
  text "Bottom Solder" at 10200.26,7110 h60
  text "Solder Resist" at 11130,7110 h60
  text "0.40mil" at 11989.77,7110 h60
  text "3.5" at 12639.6,7110 h60
  text "7" at 9790.34,6990 h60
  text "Bottom Overlay" at 10200.26,6990 h60
  text ".Layer_Name" at 577,-858.49 h60
M13 Component Bodies Top:
  text ".Layer_Name" at 577,-858.49 h60
M14 Component Bodies Bottom:
  text ".Layer_Name" at 577,-858.49 h60
M15 Courtyards Top:
  text ".Layer_Name" at 577,-858.49 h60
M16 Courtyards Bottom:
  text ".Layer_Name" at 577,-858.49 h60
Drill Drawing:
  circle w1: c5692.8,3220.83 r24.91
  lines w1: 5667.89,2598.09 5692.8,2610.54 5717.71,2598.09 5705.26,2623 5717.71,2647.9 5692.8,2635.45 5667.89,2647.9 5680.35,2623 5667.89,2598.09 ; 5667.89,2760 5680.35,2760 5692.8,2747.54 5705.26,2760 5717.71,2760 5705.26,2772.45 5717.71,2784.91 5705.26,2784.91 5692.8,2797.36 5680.35,2784.91 5667.89,2784.91 5680.35,2772.45 5667.89,2760 ; 5667.89,2946.82 5717.71,2946.82 5692.8,2897 5667.89,2946.82 ; 5667.89,3046.46 5667.89,3058.92 5680.35,3071.37 5667.89,3083.83 5667.89,3096.28 5680.35,3096.28 5692.8,3083.83 5705.26,3096.28 5717.71,3096.28 5717.71,3083.83 5705.26,3071.37 5717.71,3058.92 5717.71,3046.46 5705.26,3046.46 5692.8,3058.92 5680.35,3046.46 5667.89,3046.46
  lines w12: 5600,2553.25 7719.4,2553.25 ; 5600,3300.54 7719.4,3300.54 ; 5970.67,2403.79 5970.67,3450 ; 6327.78,2403.79 6327.78,3450 ; 6989.79,2403.79 6989.79,3450 ; 7274.14,2403.79 7274.14,3450 ; 5600,2403.79 7719.4,2403.79 7719.4,3450 5600,3450 5600,2403.79
  text "Symbol" at 5689.68,3345.38 h72
  text "Quantity" at 6015.51,3345.38 h72
  text "Finished Hole Size" at 6372.62,3345.38 h72
  text "Plated" at 7034.62,3345.38 h72
  text "Hole Type" at 7318.98,3345.38 h72
  text "16" at 6015.51,3195.92 h60
  text "7.87mil (0.200mm)" at 6372.62,3195.92 h60
  text "PTH" at 7034.62,3195.92 h60
  text "Round" at 7318.98,3195.92 h60
  text "382" at 6015.51,3046.46 h60
  text "10.00mil (0.254mm)" at 6372.62,3046.46 h60
  text "PTH" at 7034.62,3046.46 h60
  text "Round" at 7318.98,3046.46 h60
  text "6" at 6015.51,2897 h60
  text "33.46mil (0.850mm)" at 6372.62,2897 h60
  text "PTH" at 7034.62,2897 h60
  text "Round" at 7318.98,2897 h60
  text "14" at 6015.51,2747.54 h60
  text "40.00mil (1.016mm)" at 6372.62,2747.54 h60
  text "PTH" at 7034.62,2747.54 h60
  text "Round" at 7318.98,2747.54 h60
  text "12" at 6015.51,2598.09 h60
  text "51.18mil (1.300mm)" at 6372.62,2598.09 h60
  text "PTH" at 7034.62,2598.09 h60
  text "Round" at 7318.98,2598.09 h60
  text "430 Total" at 6015.51,2448.63 h60
  text ".Layer_Name" at 577,-858.49 h60

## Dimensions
0,-400 to 1000,-400 on M2 Board Dimensions
0,0 to 4000,0 on M2 Board Dimensions
0,4000 to 0,0 on M2 Board Dimensions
